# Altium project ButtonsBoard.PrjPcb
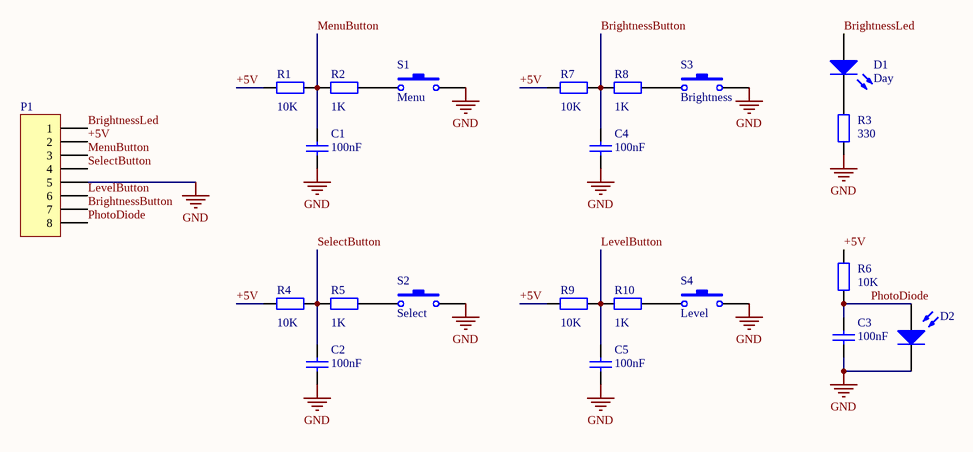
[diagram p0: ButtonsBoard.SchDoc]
1 sheet, 22 parts. Net scope: global (net labels, ports and power ports of the same name join across sheets).

## Sheet ButtonsBoard.SchDoc
size A4; PageSetup: Record=PageOptions|CenterHorizontal=True|CenterVertical=True|PrintScale=1.00|XCorrection=1.00|YCorrection=1.00|PrintKind=1|BorderSize=5000000|LeftOffset=0|BottomOffset=0|Orientation=2|PaperLength=1000|PaperWidth=1000|Scale=100|PaperSource=1|PrintQuality=300|MediaType=1|DitherType=10|PaperKind=A4|PrintScaleMode=1

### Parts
C1  value 100nF  [RAD-0.3]  (hidden comment: Cap)
C2  value 100nF  [RAD-0.3]  (hidden comment: Cap)
C3  value 100nF  [RAD-0.3]  (hidden comment: Cap)
C4  value 100nF  [RAD-0.3]  (hidden comment: Cap)
C5  value 100nF  [RAD-0.3]  (hidden comment: Cap)
D1  Day  [LED-0]
D2  Photo Sen  [PIN2]  (value not drawn)
P1  Header 8  [HDR1X8]  (value not drawn)
R1  value 10K  [AXIAL-0.4]  (hidden comment: Res2)
R2  value 1K  [AXIAL-0.4]  (hidden comment: Res2)
R3  value 330  [AXIAL-0.4]  (hidden comment: Res2)
R4  value 10K  [AXIAL-0.4]  (hidden comment: Res2)
R5  value 1K  [AXIAL-0.4]  (hidden comment: Res2)
R6  value 10K  [AXIAL-0.4]  (hidden comment: Res2)
R7  value 10K  [AXIAL-0.4]  (hidden comment: Res2)
R8  value 1K  [AXIAL-0.4]  (hidden comment: Res2)
R9  value 10K  [AXIAL-0.4]  (hidden comment: Res2)
R10  value 1K  [AXIAL-0.4]  (hidden comment: Res2)
S1  Menu  [SPST-2]
S2  Select  [SPST-2]
S3  Brightness  [SPST-2]
S4  Level  [SPST-2]

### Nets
GND: C1.1 C2.1 C3.1 C4.1 C5.1 D2.2(K) P1.5 R3.1 S1.2 S2.2 S3.2 S4.2
+5V: P1.2 R1.1 R4.1 R6.2 R7.1 R9.1
BrightnessButton: C4.2 P1.7 R7.2 R8.1
BrightnessLed: D1.1(A) P1.1
LevelButton: C5.2 P1.6 R9.2 R10.1
MenuButton: C1.2 P1.3 R1.2 R2.1
PhotoDiode: C3.2 D2.1(A) P1.8 R6.1
SelectButton: C2.2 P1.4 R4.2 R5.1
NetD1_2: D1.2(K) R3.2
NetR2_2: R2.2 S1.1
NetR5_2: R5.2 S2.1
NetR8_2: R8.2 S3.1
NetR10_2: R10.2 S4.1

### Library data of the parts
C1-C5 = Cap: Capacitor
D1 = LED0: Typical INFRARED GaAs LED
D2 = Photo Sen: Photosensitive Diode
P1 = Header 8: Header, 8-Pin
R1-R10 = Res2: Resistor
S1-S4 = SW-PB: Switch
